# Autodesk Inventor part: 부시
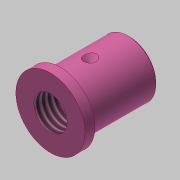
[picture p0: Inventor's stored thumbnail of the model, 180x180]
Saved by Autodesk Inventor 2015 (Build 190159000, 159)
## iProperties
Created: 2019-04
Part Number: 부시
Material: 강철, 연강
Document SubType Name: Modeling
Designer: mduedu
Density: 1 g/cm^3
Appearance: 분홍색
Author: mduedu
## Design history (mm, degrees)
sketch "스케치1"
  geometry: L1 (0, 0)-(3, 0); L2 (3, 0)-(3, 10.5); L3 (3, 10.5)-(0, 10.5); L4 (0, 10.5)-(0, 0); L5 (3, 0)-(24, 0); L6 (24, 0)-(24, 8.5); L7 (24, 8.5)-(3, 8.5); L8 (3, 8.5)-(3, 0)
  constraints: 16 end point, 4 parallel, 2 horizontal, 2 perpendicular
  dimensions: "d0" = 3 distance of L2.end L3.end; "d2" = 24 distance between parallel lines of L6 L4; "d3" = 17 diameter of L7 L5; "d4" = 21 diameter of L3 L1
revolve "회전1" sketch "스케치1" stored, may be unused: angle "d5" = 90 deg
sketch "스케치2"
  geometry: L1 (3, 8.5)-(24, 8.5) reference; L2 (12, 8.5)-(12, 6.5); L3 (12, 6.5)-(14, 8.5); L4 (0, -10.5)-(0, 10.5) reference; 1 further point
  constraints: 4 end point, 2 point on line, 1 perpendicular
  dimensions: "d6" = 12 distance from line of L2.start L4; "d7" = 2 distance of L2.start L3.end; "d8" = 45 deg angle of L3 L2
revolve "회전2" sketch "스케치2" stored, may be unused: angle "d9" = 90 deg
hole "구멍1" diameter "d12" = 10.106; stored, may be unused: countersink angle "d16" = 90 deg, drill point angle "d18" = 118 deg; dims "d10" = 10, "d11" = 10, "d13" = 39, "d14" = 4, "d15" = 2, "d17" = 8
chamfer "모따기1" distance "d19" = 0.5; stored, may be unused: second distance "d20" = 2, angle "d21" = 45 deg
node "작업점1"
  node "작업 평면1"
  node "작업축1"
node "솔리드1"
